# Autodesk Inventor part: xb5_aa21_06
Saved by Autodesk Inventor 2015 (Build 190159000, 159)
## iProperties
Created: 2018-05
Part Number: xb5_aa21_06
Checked By: TraceParts S.A.
Material: Generic
Catalog Web Link: www.traceparts.com
Document SubType Name: Modeling
Designer: TraceParts
Density: 1 g/cm^3
Appearance: Default
Company: TraceParts S.A.
Author: TraceParts
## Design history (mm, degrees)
feature "xb5_aa21_06.ipt"
body "Solid1"
